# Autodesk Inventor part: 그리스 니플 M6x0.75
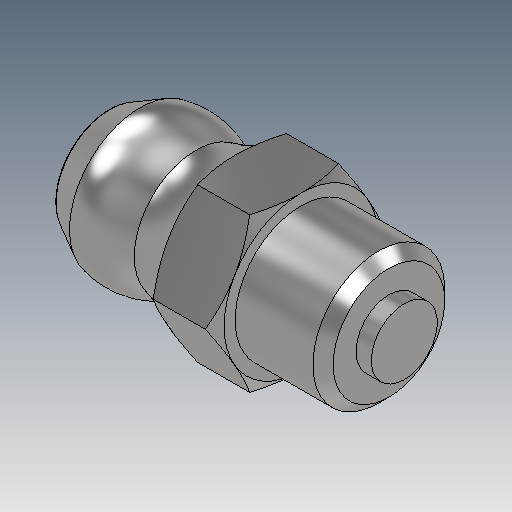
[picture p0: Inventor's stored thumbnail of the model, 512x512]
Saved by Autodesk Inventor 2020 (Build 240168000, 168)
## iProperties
Created: 2024-11
Part Number: 그리스 니플 M6x0.75
Material: 강철, 연강
Description: 윤활 니플, 원추 유형 A
Document SubType Name: Modeling
Designer: shin
Density: 7.85 g/cm^3
Appearance: 기본값
Author: jhkim
Sending System: Autodesk Inventor 2025
Preprocessor: ST-DEVELOPER v20
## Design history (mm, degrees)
feature "Solid1"
node "솔리드1"
